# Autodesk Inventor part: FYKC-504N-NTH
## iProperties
Company: Engineering Services Northland (1988) Ltd
Author: Malcolm
Shininess: 60.0
PropertySet Name: _Private Model Information
Created: 2001-06
Part Number: FYKC-504N-NTH
Material: Stainless Steel, Austenitic
Description: 4 Hole Flange S/S Bearing 20mm
Document SubType Name: Modeling
Designer: Malcolm
Control State: 0
Master: False
Checked Out: False
PropertySet Name: Design Tracking Control
Density: 0.0
Volumn: 0.0
Area: 0.0
PropertySet Name: Model Information
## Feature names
1. Revolution1
2. Hole1
3. Hole2
4. Fillet1
5. Extrusion1
6. Extrusion2
7. Extrusion3
8. Fillet2
9. Extrusion4
10. Extrusion5
11. Fillet3
12. Fillet4
13. Fillet5
14. Fillet6
15. Extrusion6
16. Fillet7
